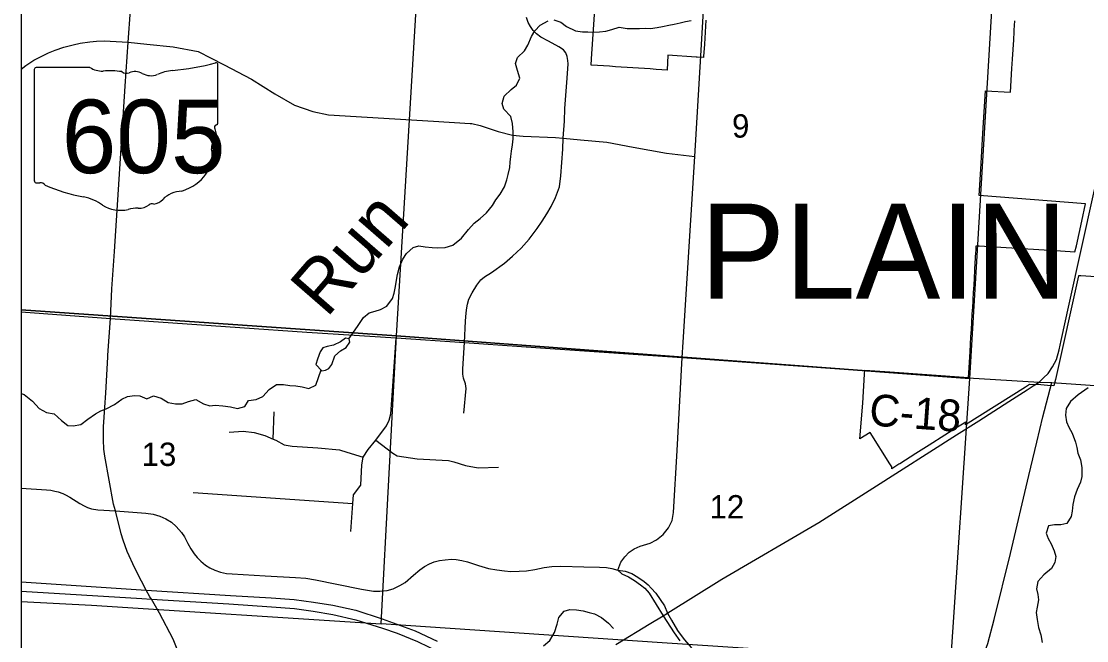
# Model space of a CAD drawing. Extents: x 0 to 91.3, y -0.7 to 22.
# Drawn here: x 2.1 to 4.012, y 18.226 to 19.336 of the extents above; entities that cross this region are included whole.
import ezdxf

# ---------------------------------------------------------------- set-up
doc = ezdxf.new("R2010")
doc.units = 0
for name, color, linetype in [('GM_X_City_Street', 7, 'Continuous'), ('GM_X_Corporation', 7, 'Continuous'), ('GM_X_County_Road', 7, 'Continuous'), ('GM_X_County_Road_Text', 7, 'Continuous'), ('GM_X_Minor_Lake', 7, 'Continuous'), ('GM_X_Minor_River', 7, 'Continuous'), ('GM_X_Minor_River_Text', 7, 'Continuous'), ('GM_X_Section_Text', 7, 'Continuous'), ('GM_X_State_Location', 7, 'Continuous'), ('GM_X_State_Route', 7, 'Continuous'), ('GM_X_State_Shield', 7, 'Continuous'), ('GM_X_Township_Road', 7, 'Continuous'), ('GM_X_Township_Text', 7, 'Continuous'), ('GM_X_US_Route', 7, 'Continuous'), ('SH_Data', 7, 'Continuous')]:
    doc.layers.add(name, color=color, linetype=linetype)

msp = doc.modelspace()

# ---------------------------------------------------------------- linework, layer by layer
at = {"layer": 'GM_X_City_Street'}
for p, q in [((2.552, 18.5873), (2.5537, 18.6361)), ((2.4083, 18.4911), (2.6947, 18.4719))]:
    msp.add_line(p, q, dxfattribs=at)
for points in [[(2.8953, 18.7603), (2.8973, 18.7984), (2.8984, 18.8134), (2.8995, 18.8225), (2.9006, 18.8293), (2.9031, 18.838), (2.9091, 18.8493), (2.9173, 18.8635), (2.9249, 18.8725), (2.9315, 18.8782), (2.9438, 18.8859), (2.9673, 18.9028), (2.9818, 18.9151), (2.9968, 18.9296), (3.0116, 18.946), (3.0255, 18.9649), (3.0348, 18.9777), (3.0433, 18.9909), (3.0512, 19.004), (3.0586, 19.0206), (3.0657, 19.0395), (3.0682, 19.0592), (3.072, 19.1073), (3.0725, 19.1267), (3.0747, 19.1576), (3.0755, 19.18), (3.0794, 19.2347), (3.0813, 19.2604), (3.081, 19.2659), (3.0799, 19.2732), (3.0772, 19.2798), (3.0728, 19.2853), (3.0649, 19.2907), (3.0463, 19.3006), (3.0321, 19.3082), (3.0244, 19.314), (3.0187, 19.32), (3.014, 19.3268), (3.0097, 19.3345), (3.0069, 19.3435)], [(2.1, 19.2508), (2.1083, 19.2572), (2.1227, 19.2667), (2.1371, 19.2741), (2.1487, 19.2796), (2.1605, 19.2845), (2.1766, 19.2902), (2.1933, 19.2945), (2.2059, 19.2972), (2.2228, 19.2994), (2.2347, 19.3007), (2.2486, 19.3014), (2.292, 19.2987)], [(2.292, 19.2987), (2.3254, 19.2952), (2.3726, 19.2909), (2.4176, 19.2824), (2.4642, 19.2583), (2.5131, 19.2328), (2.5548, 19.2064), (2.5905, 19.186), (2.623, 19.1748), (2.6515, 19.1687), (2.8399, 19.1575), (2.9056, 19.1534)], [(2.9056, 19.1534), (2.9087, 19.1532), (2.9236, 19.1494), (2.9557, 19.1387), (2.9814, 19.1323), (3.0007, 19.1302), (3.0586, 19.128), (3.0725, 19.1267), (3.1036, 19.1237), (3.1508, 19.1194), (3.198, 19.1109), (3.258, 19.1001), (3.3086, 19.0942)], [(2.6911, 18.4213), (2.6947, 18.4719), (2.6959, 18.4875), (2.7094, 18.5048), (2.7113, 18.5412), (2.7135, 18.5547), (2.7225, 18.5686), (2.736, 18.5854), (2.7553, 18.6109), (2.7604, 18.6212), (2.7634, 18.6323), (2.7664, 18.6738), (2.7726, 18.7688)], [(2.8943, 18.6338), (2.8981, 18.6781), (2.8973, 18.6863), (2.8938, 18.6964), (2.8921, 18.7038), (2.8921, 18.7131), (2.8953, 18.7603)], [(2.4728, 18.5993), (2.4979, 18.6012), (2.5179, 18.5991), (2.5372, 18.5935), (2.552, 18.5873), (2.5567, 18.5853), (2.5718, 18.5771), (2.5861, 18.5743), (2.6323, 18.5717), (2.6709, 18.5681), (2.6845, 18.5638), (2.7135, 18.5547)], [(2.736, 18.5854), (2.7667, 18.5619), (2.7746, 18.5569), (2.8105, 18.5518), (2.8669, 18.5488), (2.876, 18.5464), (2.8971, 18.5396), (2.9202, 18.5359), (2.9566, 18.5369)], [(2.1, 18.499), (2.1454, 18.4961), (2.1528, 18.4953), (2.1602, 18.494), (2.1663, 18.4924), (2.1743, 18.4898), (2.1793, 18.4873), (2.1868, 18.483), (2.2049, 18.4717), (2.2126, 18.4674), (2.2189, 18.4646), (2.2259, 18.4623), (2.2372, 18.4603), (2.269, 18.4583), (2.3237, 18.4541), (2.3367, 18.4523), (2.3485, 18.4487), (2.3594, 18.444), (2.3696, 18.4379), (2.3781, 18.4305), (2.3873, 18.4199), (2.3929, 18.4117), (2.399, 18.4001), (2.4045, 18.3903), (2.4102, 18.3815), (2.4154, 18.3748), (2.4219, 18.3682), (2.4307, 18.3609), (2.4382, 18.3562), (2.4474, 18.3523), (2.4577, 18.3486), (2.4684, 18.3464), (2.4785, 18.3457), (2.5378, 18.3422), (2.5919, 18.3391), (2.6106, 18.3376), (2.6281, 18.3347), (2.6665, 18.327), (2.7107, 18.3179), (2.7321, 18.3144), (2.7436, 18.3142), (2.7563, 18.3157), (2.7671, 18.3188), (2.7794, 18.3244), (2.7888, 18.3302), (2.804, 18.3433), (2.8153, 18.3527), (2.8238, 18.3587), (2.8323, 18.3632), (2.8411, 18.3668), (2.8506, 18.3693), (2.8605, 18.3708), (2.8722, 18.3717), (2.8807, 18.3711), (2.8903, 18.3697), (2.9008, 18.3669), (2.9204, 18.3603), (2.9384, 18.3551), (2.9537, 18.3525), (2.9674, 18.3509), (2.9785, 18.3499), (2.9935, 18.3501), (3.0065, 18.3512), (3.0215, 18.3535), (3.0384, 18.3566), (3.0521, 18.3584), (3.0685, 18.3594), (3.1097, 18.3583), (3.1379, 18.3577), (3.15, 18.3568), (3.1599, 18.355), (3.1703, 18.3521)], [(3.1703, 18.3521), (3.1778, 18.3458), (3.1896, 18.3401), (3.2004, 18.3336), (3.2115, 18.326), (3.2188, 18.3199), (3.2268, 18.3111), (3.2521, 18.2705)], [(3.1703, 18.3521), (3.1838, 18.3506), (3.1958, 18.3459), (3.2067, 18.3394), (3.2178, 18.3318), (3.225, 18.3257), (3.2303, 18.3197), (3.2388, 18.3107), (3.2541, 18.2884), (3.2596, 18.2752)], [(3.2521, 18.2705), (3.2718, 18.24), (3.2817, 18.2251)], [(3.2596, 18.2752), (3.2669, 18.2624), (3.2775, 18.244), (3.2897, 18.2275), (3.3029, 18.2131)]]:
    msp.add_lwpolyline(points, dxfattribs=at)
at = {"layer": 'GM_X_Corporation'}
for points in [[(4.7833, 18.1361), (4.8242, 18.6326), (4.8251, 18.6439), (4.8263, 18.646), (4.8271, 18.6491), (4.8277, 18.656), (4.8336, 18.7529), (4.834, 18.7568), (4.8352, 18.7619), (4.9205, 20.3667), (4.9376, 20.6305), (4.9448, 20.7239), (3.9216, 20.777), (3.4006, 20.8086), (3.3908, 20.8093), (3.2209, 20.8181), (3.0994, 20.8263), (2.3878, 20.8673), (2.1, 20.8844), (2.1, 14.1)], [(4.7833, 18.1361), (4.8242, 18.6326), (4.8251, 18.6439), (4.8263, 18.646), (4.8271, 18.6491), (4.8277, 18.656), (4.8336, 18.7529), (4.834, 18.7568), (4.8352, 18.7619), (4.9205, 20.3667), (4.9376, 20.6305), (4.9448, 20.7239), (3.9216, 20.777), (3.4006, 20.8086), (3.3908, 20.8093), (3.2209, 20.8181), (3.0994, 20.8263), (2.3878, 20.8673), (2.1, 20.8844), (2.1, 15.7138)], [(2.1, 19.7378), (2.1, 15.7194)], [(3.3285, 19.3382), (3.326, 19.2957), (3.3246, 19.2731), (3.3245, 19.2715), (3.3132, 19.272), (3.3112, 19.2722), (3.2601, 19.2755), (3.2593, 19.2489), (3.2495, 19.2496), (3.2391, 19.2502), (3.2287, 19.2509), (3.2183, 19.2516), (3.2079, 19.2523), (3.1975, 19.253), (3.1871, 19.2536), (3.1767, 19.2543), (3.1663, 19.255), (3.1559, 19.2557), (3.1342, 19.2571), (3.1228, 19.2578), (3.1234, 19.2692), (3.1257, 19.3044), (3.1304, 19.3758)], [(4.0917, 18.8738), (4.0013, 18.8798), (3.9975, 18.88), (3.9558, 18.6942), (3.9539, 18.6848), (3.9533, 18.6826), (3.9418, 18.6835), (3.9298, 18.6845), (3.9095, 18.6852), (3.9023, 18.6805), (3.7946, 18.6128), (3.7949, 18.6175), (3.7889, 18.6141), (3.7829, 18.6105), (3.7771, 18.6067), (3.7574, 18.5941), (3.7292, 18.5763), (3.7052, 18.5611), (3.6767, 18.543), (3.675, 18.5421), (3.6621, 18.5339), (3.6622, 18.5373), (3.659, 18.5426), (3.6234, 18.599), (3.6051, 18.5877), (3.6103, 18.6514), (3.6133, 18.7037), (3.6137, 18.7106), (3.659, 18.7077), (3.8001, 18.6978), (3.8005, 18.7054), (3.8028, 18.7442), (3.8036, 18.7574), (3.8043, 18.7706), (3.8051, 18.7839), (3.8059, 18.7971), (3.8067, 18.811), (3.8074, 18.8236), (3.8081, 18.8345), (3.8082, 18.8368), (3.809, 18.85), (3.8094, 18.8567), (3.8098, 18.8633), (3.8106, 18.8765), (3.8113, 18.8897), (3.8115, 18.8919), (3.8132, 18.9222), (3.8134, 18.9247), (3.8139, 18.934), (3.819, 18.9339), (3.965, 18.9245), (3.991, 18.9228), (3.9935, 18.9339), (4.0031, 18.9782), (4.0098, 19.0091), (3.8192, 19.024), (3.822, 19.0713), (3.8258, 19.1356), (3.8303, 19.2119), (3.8754, 19.2092), (3.8779, 19.2515), (3.879, 19.2685), (3.88, 19.2859), (3.881, 19.3029), (3.8819, 19.3173), (3.8821, 19.3203), (3.8831, 19.3373)]]:
    msp.add_lwpolyline(points, dxfattribs=at)
for points in [[(2.1, 19.8366), (2.1, 18.819), (2.7736, 18.7721), (2.8346, 19.7864)], [(2.8346, 19.7864), (3.8634, 19.7265), (3.8019, 18.6958), (2.7736, 18.7721)], [(2.1, 18.819), (2.1, 18.2962), (2.2257, 18.2891), (2.7457, 18.2558), (2.7736, 18.7721)], [(3.8019, 18.6958), (3.7678, 18.1877), (3.2499, 18.2218), (2.7457, 18.2558), (2.7736, 18.7721)]]:
    msp.add_lwpolyline(points, close=True, dxfattribs=at)
at = {"layer": 'GM_X_County_Road'}
for p, q in [((2.1, 18.8152), (2.2599, 18.8035)), ((3.9269, 18.6895), (3.9497, 18.6887)), ((3.9497, 18.6887), (4.0096, 18.6845))]:
    msp.add_line(p, q, dxfattribs=at)
for points in [[(2.2599, 18.8035), (2.3722, 18.7957), (2.6123, 18.7791), (2.7726, 18.7688), (2.8953, 18.7603), (3.032, 18.7508), (3.2863, 18.7332)], [(3.2863, 18.7332), (3.5681, 18.7134), (3.6139, 18.7101), (3.6269, 18.7092)], [(3.6269, 18.7092), (3.7686, 18.6988), (3.7964, 18.6972)], [(3.6222, 17.9453), (3.6733, 17.9996), (3.7616, 18.0953), (3.7814, 18.1194), (3.7906, 18.1309), (3.8043, 18.1522), (3.8145, 18.1715), (3.8203, 18.1847), (3.8262, 18.1972), (3.8345, 18.2206), (3.846, 18.2638), (3.8752, 18.3822), (3.908, 18.5219), (3.9227, 18.5819), (3.9334, 18.627), (3.9497, 18.6887)], [(3.7964, 18.6972), (3.7994, 18.697), (3.9269, 18.6895)], [(4.0096, 18.6845), (4.0345, 18.6828), (4.1701, 18.6744), (4.3697, 18.6624)]]:
    msp.add_lwpolyline(points, dxfattribs=at)
at = {"layer": 'GM_X_Minor_Lake'}
for points in [[(2.6396, 18.7098), (2.6457, 18.7109), (2.6521, 18.7139), (2.6571, 18.7207), (2.6625, 18.7366), (2.6728, 18.7453), (2.6831, 18.7517), (2.6896, 18.7608), (2.6885, 18.7668), (2.6821, 18.7684), (2.6729, 18.7616), (2.6604, 18.7556), (2.649, 18.7534), (2.641, 18.7508), (2.6364, 18.7436), (2.6314, 18.7308), (2.6286, 18.7209)], [(2.6286, 18.7209), (2.6396, 18.7098)]]:
    msp.add_lwpolyline(points, dxfattribs=at)
at = {"layer": 'GM_X_Minor_River'}
for points in [[(2.6875, 18.7671), (2.7031, 18.7892), (2.7142, 18.805), (2.7245, 18.8137), (2.7351, 18.8167), (2.7446, 18.8196), (2.7561, 18.8256), (2.7664, 18.8392), (2.7691, 18.8487), (2.7718, 18.8608), (2.7734, 18.8722), (2.7754, 18.8821), (2.7785, 18.8961), (2.7847, 18.9101), (2.7912, 18.9199), (2.803, 18.9309), (2.8133, 18.9335), (2.8246, 18.9322), (2.8372, 18.9306), (2.8478, 18.9302), (2.8607, 18.9309), (2.8744, 18.935), (2.89, 18.9474), (2.9026, 18.9633), (2.9126, 18.9742), (2.9233, 18.9825), (2.9351, 18.9931), (2.9454, 19.0059), (2.9519, 19.0165), (2.9592, 19.0263), (2.9669, 19.0395), (2.9711, 19.0524), (2.9738, 19.0619), (2.977, 19.074), (2.9774, 19.0839), (2.9786, 19.0941), (2.9798, 19.1036), (2.9818, 19.115), (2.9826, 19.1256), (2.983, 19.1381), (2.9816, 19.1533), (2.9787, 19.1655), (2.9662, 19.1788), (2.9629, 19.1887), (2.9667, 19.202), (2.979, 19.214), (2.9889, 19.2216), (2.9946, 19.2344), (2.9906, 19.2481), (2.9868, 19.261), (2.9903, 19.2716), (3.0033, 19.2837), (3.0091, 19.2935), (3.0156, 19.3091), (3.0214, 19.3193), (3.0309, 19.3295), (3.0454, 19.3373)], [(3.0556, 19.3392), (3.0681, 19.3349), (3.0787, 19.3273), (3.0946, 19.3196), (3.1071, 19.3176), (3.117, 19.3176), (3.1265, 19.3171), (3.1375, 19.3174), (3.1489, 19.3185), (3.1595, 19.3215), (3.1732, 19.326), (3.1876, 19.3236), (3.2092, 19.3235), (3.2195, 19.3238), (3.2294, 19.3237), (3.2411, 19.3252), (3.2506, 19.327), (3.262, 19.3292), (3.2719, 19.3311), (3.2822, 19.3337), (3.2921, 19.3359), (3.3023, 19.3377)], [(2.1, 18.6689), (2.1054, 18.6672), (2.1201, 18.6549), (2.1322, 18.6423), (2.1454, 18.6347), (2.1587, 18.6323), (2.1719, 18.6208), (2.1836, 18.6117), (2.1931, 18.6108), (2.2067, 18.6134), (2.2193, 18.6228), (2.233, 18.6322), (2.2429, 18.6379), (2.2525, 18.6416), (2.2673, 18.6495), (2.2806, 18.6585), (2.2905, 18.6634), (2.3031, 18.6652), (2.3126, 18.6648), (2.325, 18.6594), (2.3372, 18.665), (2.3509, 18.6607), (2.3637, 18.6527), (2.3766, 18.6503), (2.3884, 18.6503), (2.4002, 18.6547), (2.4135, 18.6581), (2.4267, 18.6504), (2.4384, 18.6469), (2.4479, 18.648), (2.4616, 18.6468), (2.4752, 18.6448), (2.4881, 18.6421), (2.501, 18.6458), (2.5076, 18.6564), (2.5216, 18.6582), (2.5334, 18.6638), (2.5449, 18.6763), (2.5578, 18.6849), (2.5707, 18.6848), (2.5817, 18.6832), (2.5924, 18.6828), (2.6041, 18.6808), (2.6162, 18.6777), (2.6288, 18.6841), (2.6381, 18.7113)], [(4.0148, 18.6793), (3.9968, 18.6668), (3.9831, 18.6544), (3.9754, 18.6423), (3.9742, 18.6302), (3.9757, 18.618), (3.9802, 18.6085), (3.9862, 18.5978), (3.9918, 18.5819), (3.9944, 18.572), (3.9962, 18.5621), (4.0007, 18.5499), (4.0032, 18.5363), (4.0035, 18.5199), (4.0008, 18.5101), (3.995, 18.4968), (3.99, 18.4836), (3.9873, 18.4699), (3.9857, 18.4578), (3.9841, 18.4483), (3.9761, 18.4359), (3.9658, 18.4333), (3.9544, 18.4333), (3.9434, 18.4315), (3.9391, 18.4186), (3.9429, 18.4087), (3.9481, 18.3992), (3.9537, 18.387), (3.9567, 18.3764), (3.9547, 18.3658), (3.9486, 18.3548), (3.9352, 18.3435), (3.9245, 18.3318)], [(3.9245, 18.3318), (3.9222, 18.3185), (3.9244, 18.3087), (3.9255, 18.2992), (3.9231, 18.2859), (3.9215, 18.276), (3.9234, 18.2639), (3.9256, 18.2494), (3.93, 18.2361), (3.9322, 18.2225)], [(3.0369, 18.2164), (3.0483, 18.2258), (3.0572, 18.2402), (3.0614, 18.255), (3.0649, 18.2671), (3.0745, 18.2784), (3.0844, 18.2818), (3.0965, 18.2809), (3.1086, 18.279), (3.1192, 18.2762), (3.1287, 18.2739), (3.1412, 18.2674), (3.154, 18.2571), (3.1627, 18.2475)]]:
    msp.add_lwpolyline(points, dxfattribs=at)
at = {"layer": 'GM_X_State_Route'}
for p, q in [((2.2554, 18.7377), (2.2599, 18.8035)), ((2.1, 18.3144), (2.3166, 18.301))]:
    msp.add_line(p, q, dxfattribs=at)
for points in [[(2.2599, 18.8035), (2.2625, 18.8564), (2.2672, 18.9235), (2.2866, 19.2202), (2.292, 19.2987), (2.3, 19.4144)], [(2.2499, 18.6439), (2.2515, 18.6701), (2.2552, 18.7339), (2.2554, 18.7377)], [(2.3309, 18.3045), (2.3243, 18.3164), (2.3155, 18.3323), (2.3036, 18.3557), (2.2899, 18.3856), (2.2826, 18.4061), (2.2792, 18.417), (2.269, 18.4583), (2.2657, 18.4706), (2.2497, 18.5568), (2.2484, 18.5689), (2.2473, 18.5857), (2.2477, 18.6092), (2.2499, 18.6439)], [(2.1, 18.3312), (2.3243, 18.3164), (2.4753, 18.3067), (2.5484, 18.3027), (2.5899, 18.2994), (2.6242, 18.2948), (2.6591, 18.2893), (2.7001, 18.2801), (2.7479, 18.265), (2.8069, 18.2433), (2.8463, 18.2248)], [(2.3166, 18.301), (2.3334, 18.3), (2.4724, 18.2915), (2.549, 18.2865), (2.59, 18.2832), (2.624, 18.2788), (2.6593, 18.2725), (2.7003, 18.2632), (2.7481, 18.2481), (2.7743, 18.2391), (2.8113, 18.2243), (2.8503, 18.2052), (2.8914, 18.1825), (2.9291, 18.158), (2.9578, 18.1369), (2.9789, 18.1194)], [(2.412, 18.1148), (2.4022, 18.1499), (2.3962, 18.1667), (2.3888, 18.1885), (2.3724, 18.2281), (2.348, 18.2751), (2.3334, 18.3), (2.3309, 18.3045)]]:
    msp.add_lwpolyline(points, dxfattribs=at)
at = {"layer": 'GM_X_State_Shield'}
for p, q in [((2.4529, 19.1539), (2.4529, 19.2585)), ((2.1233, 19.2501), (2.1233, 19.05)), ((2.2231, 19.2536), (2.1266, 19.2536)), ((2.4529, 19.1539), (2.4529, 19.1539))]:
    msp.add_line(p, q, dxfattribs=at)
for centre, major_axis, start_param, end_param in [((2.3355, 19.5264), (0.3495, 0), 4.814394, 5.042369), ((2.4493, 19.259), (0.00367, 0), 6.141152, 7.989035), ((2.1271, 19.2506), (0.00382, 0), 1.712693, 3.28349), ((2.2461, 19.2768), (0.037, 0), 4.042523, 4.731795), ((2.2584, 19.1412), (0.133, 0), 1.404758, 1.657858), ((2.2886, 19.2516), (0.0107, 0), 3.836095, 5.185415), ((2.3042, 19.2285), (0.0222, 0), 0.950623, 2.079405), ((2.3329, 19.2602), (0.0267, 0), 4.081561, 5.145723), ((2.3801, 19.1925), (0.0703, 0), 1.699011, 2.107814), ((2.4521, 19.1462), (0.00568, 0), 1.883978, 3.671073), ((2.416, 19.1329), (0.0341, 0), 5.934695, 6.695948), ((2.449, 19.1535), (0.00393, 0), 5.05454, 6.418171), ((2.4661, 19.1101), (0.0248, 0), 2.387724, 3.262537), ((2.3551, 19.0967), (0.0874, 0), 5.101752, 6.440018), ((2.1272, 19.0496), (0.00385, 0), 3.00124, 4.508301), ((2.1277, 19.0701), (0.0294, 0), 4.665946, 4.897461), ((2.1338, 19.0385), (0.0106, 0), 0.519207, 1.627899), ((2.2676, 19.2183), (0.2524, 0), 4.195997, 4.488961), ((2.392, 18.9938), (0.0479, 0), 1.647645, 2.488434), ((2.1923, 18.9601), (0.079, 0), 0.823519, 1.323587), ((2.2777, 19.0375), (0.0501, 0), 4.026481, 4.996735), ((2.3104, 19.0225), (0.0267, 0), 4.691044, 5.507374), ((2.3345, 19.0031), (0.00752, 0), 1.147584, 2.315152), ((2.3313, 19.0306), (0.0282, 0), 4.937069, 5.64225), ((2.3067, 18.9683), (0.0412, 0), 1.495662, 1.94098)]:
    msp.add_ellipse(centre, major_axis=major_axis, ratio=0.8, start_param=start_param, end_param=end_param, dxfattribs=at)
at = {"layer": 'GM_X_Township_Road'}
for p, q in [((3.3086, 19.0942), (3.3193, 19.2743)), ((3.288, 18.7609), (3.3086, 19.0942))]:
    msp.add_line(p, q, dxfattribs=at)
for points in [[(3.3193, 19.2743), (3.3279, 19.4173), (3.3467, 19.7553)], [(3.1703, 18.3521), (3.1762, 18.3665), (3.1832, 18.3763), (3.191, 18.3841), (3.2001, 18.3904), (3.2108, 18.3952), (3.2288, 18.4008), (3.2398, 18.4065), (3.2521, 18.4162), (3.2615, 18.4282), (3.2678, 18.4414), (3.2706, 18.4553), (3.2768, 18.5667), (3.2863, 18.7332), (3.288, 18.7609)]]:
    msp.add_lwpolyline(points, dxfattribs=at)
at = {"layer": 'GM_X_US_Route'}
msp.add_line((3.9269, 18.6895), (3.9344, 18.6968), dxfattribs=at)
for points in [[(3.9807, 18.8292), (4.0247, 19.0288), (4.0635, 19.1971), (4.0985, 19.2652)], [(3.9344, 18.6968), (3.9426, 18.7049), (3.9508, 18.7169), (3.9579, 18.7301), (3.9624, 18.747), (3.9662, 18.7637), (3.9807, 18.8292)], [(3.8182, 18.6201), (3.8724, 18.6543), (3.9053, 18.6754), (3.9162, 18.6824), (3.9269, 18.6895)], [(3.2605, 18.2757), (3.3575, 18.3357), (3.5314, 18.4374), (3.6281, 18.4989), (3.7782, 18.5948), (3.8182, 18.6201)], [(3.2266, 18.255), (3.2521, 18.2705), (3.2596, 18.2752), (3.2605, 18.2757)], [(3.1671, 18.2187), (3.1697, 18.2203), (3.2266, 18.255)]]:
    msp.add_lwpolyline(points, dxfattribs=at)
at = {"layer": 'SH_Data'}
msp.add_line((2.1, 20.9), (2.1, 14.1), dxfattribs=at)

# ---------------------------------------------------------------- texts
at = {"layer": 'GM_X_County_Road_Text'}
msp.add_text('C-18', height=0.05682, rotation=355.8896, dxfattribs=at).set_placement((3.6205, 18.6118))
at = {"layer": 'GM_X_Minor_River_Text'}
msp.add_text('Run', height=0.09469, rotation=48.9775, dxfattribs=at).set_placement((2.6477, 18.8029))
at = {"layer": 'GM_X_Section_Text'}
for s, height, p in [('9', 0.0419, (3.3755, 19.1278)), ('13', 0.04186, (2.3159, 18.539)), ('12', 0.04186, (3.3351, 18.4448))]:
    msp.add_text(s, height=height, rotation=0, dxfattribs=at).set_placement(p)
at = {"layer": 'GM_X_State_Location'}
msp.add_text('605', height=0.000189, rotation=0, dxfattribs=at).set_placement((2.2176, 19.123))
for s in ['s', 'r']:
    msp.add_text(s, height=0.000189, dxfattribs=at).set_placement((2.2844, 19.1368))
at = {"layer": 'GM_X_State_Shield'}
msp.add_text('605', height=0.13184, dxfattribs=at).set_placement((2.1725, 19.0641))
at = {"layer": 'GM_X_Township_Text'}
msp.add_text('PLAIN', height=0.17045, rotation=0, dxfattribs=at).set_placement((3.3185, 18.839))

doc.saveas('drawing.dxf')
